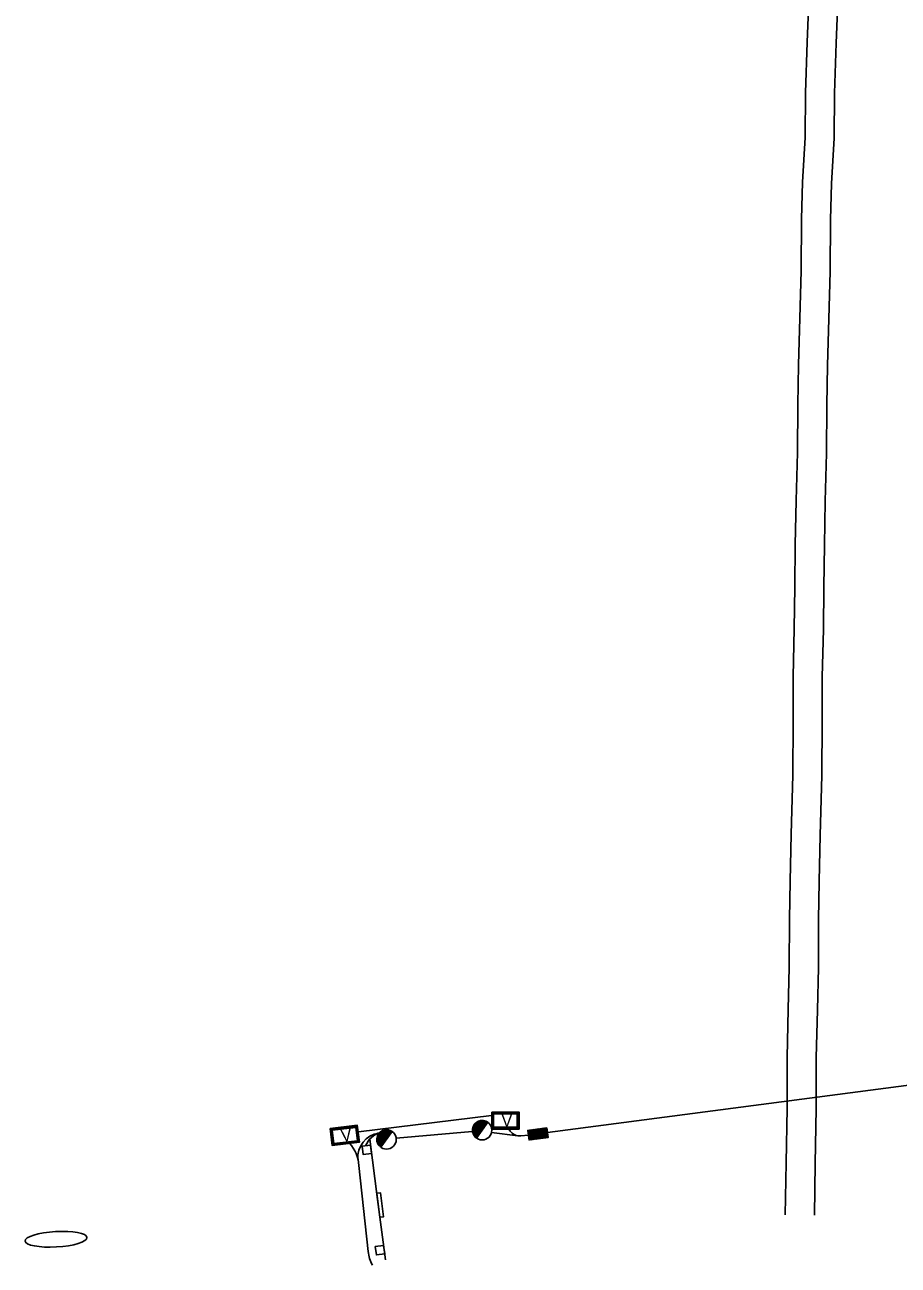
# Model space of a CAD drawing. Extents: x 584850 to 602551, y 145475 to 158627.
# Drawn here: x 585400 to 585761, y 156180 to 156692 of the extents above; entities that cross this region are included whole.
import ezdxf

# ---------------------------------------------------------------- set-up
doc = ezdxf.new("R2010")
doc.units = 0
doc.layers.add('Default', color=7, linetype='Continuous')
doc.layers.add('P_ML_LANE_LINE_50', color=7, linetype='Continuous')

msp = doc.modelspace()

# ---------------------------------------------------------------- linework, layer by layer
at = {"layer": 'Default'}
for p, q in [((585616.41, 156234.38), (585881.92, 156269.31)), ((585538.26, 156234.74), (585593.17, 156241.5)), ((585552.02, 156234.62), (585546.47, 156233.71)), ((585552.11, 156234.88), (585546.65, 156233.98)), ((585551.79, 156235.07), (585546.89, 156234.26)), ((585551.42, 156235.25), (585547.16, 156234.55)), ((585547.38, 156234.72), (585548.26, 156229.38)), ((585547.52, 156228.34), (585552.18, 156234.84)), ((585550.98, 156235.42), (585547.57, 156234.86)), ((585547.6, 156234.89), (585548.46, 156229.66)), ((585547.82, 156235.03), (585548.66, 156229.93)), ((585548.05, 156235.14), (585548.86, 156230.21)), ((585550.32, 156235.56), (585548.16, 156235.2)), ((585548.27, 156235.26), (585549.06, 156230.49)), ((585548.5, 156235.34), (585549.25, 156230.76)), ((585548.73, 156235.42), (585549.45, 156231.04)), ((585548.96, 156235.49), (585549.65, 156231.31)), ((585549.2, 156235.52), (585549.85, 156231.59)), ((585549.44, 156235.56), (585550.04, 156231.86)), ((585549.68, 156235.58), (585550.24, 156232.14)), ((585549.92, 156235.57), (585550.44, 156232.42)), ((585550.16, 156235.57), (585550.64, 156232.69)), ((585550.41, 156235.54), (585550.84, 156232.97)), ((585550.66, 156235.49), (585551.03, 156233.24)), ((585550.92, 156235.44), (585551.23, 156233.52)), ((585551.17, 156235.35), (585551.43, 156233.8)), ((585551.43, 156235.25), (585551.63, 156234.07)), ((585551.7, 156235.13), (585551.82, 156234.35)), ((585551.97, 156234.97), (585552.02, 156234.62)), ((585552.14, 156234.86), (585552.15, 156234.8)), ((585553.87, 156232.08), (585585.25, 156234.85)), ((585589.97, 156236.23), (585585.38, 156235.47)), ((585589.77, 156235.95), (585585.39, 156235.23)), ((585590.16, 156236.5), (585585.4, 156235.72)), ((585585.41, 156235.84), (585585.76, 156233.72)), ((585589.57, 156235.68), (585585.41, 156234.99)), ((585590.36, 156236.78), (585585.42, 156235.96)), ((585589.37, 156235.4), (585585.43, 156234.75)), ((585590.56, 156237.06), (585585.47, 156236.22)), ((585589.18, 156235.12), (585585.48, 156234.52)), ((585590.76, 156237.33), (585585.53, 156236.47)), ((585585.54, 156236.51), (585586.1, 156233.13)), ((585588.98, 156234.85), (585585.55, 156234.28)), ((585590.96, 156237.61), (585585.6, 156236.73)), ((585585.71, 156236.97), (585586.41, 156232.73)), ((585591.15, 156237.88), (585585.72, 156236.99)), ((585591.35, 156238.16), (585585.83, 156237.25)), ((585585.89, 156237.36), (585586.7, 156232.43)), ((585591.55, 156238.43), (585586, 156237.52)), ((585586.08, 156237.65), (585586.98, 156232.2)), ((585591.64, 156238.69), (585586.18, 156237.79)), ((585586.28, 156237.93), (585587.2, 156232.37)), ((585591.32, 156238.88), (585586.42, 156238.08)), ((585586.49, 156238.15), (585587.4, 156232.64)), ((585590.95, 156239.06), (585586.69, 156238.36)), ((585586.7, 156238.37), (585587.59, 156232.92)), ((585586.91, 156238.53), (585587.79, 156233.19)), ((585587.04, 156232.15), (585591.7, 156238.65)), ((585590.51, 156239.24), (585587.09, 156238.67)), ((585587.13, 156238.7), (585587.99, 156233.47)), ((585587.35, 156238.84), (585588.19, 156233.75)), ((585587.57, 156238.96), (585588.38, 156234.02)), ((585589.85, 156239.37), (585587.68, 156239.01)), ((585587.8, 156239.07), (585588.58, 156234.3)), ((585588.03, 156239.15), (585588.78, 156234.57)), ((585588.26, 156239.23), (585588.98, 156234.85)), ((585588.49, 156239.3), (585589.18, 156235.12)), ((585588.73, 156239.33), (585589.37, 156235.4)), ((585588.96, 156239.37), (585589.57, 156235.68)), ((585589.2, 156239.39), (585589.77, 156235.95)), ((585589.45, 156239.39), (585589.97, 156236.23)), ((585589.69, 156239.38), (585590.16, 156236.5)), ((585589.94, 156239.35), (585590.36, 156236.78)), ((585590.19, 156239.3), (585590.56, 156237.06)), ((585590.44, 156239.25), (585590.76, 156237.33)), ((585590.7, 156239.16), (585590.96, 156237.61)), ((585590.96, 156239.06), (585591.15, 156237.88)), ((585591.22, 156238.94), (585591.35, 156238.16)), ((585591.49, 156238.78), (585591.55, 156238.43)), ((585591.67, 156238.68), (585591.68, 156238.61)), ((585600.94, 156235.05), (585600.35, 156235.84)), ((585608.25, 156235.05), (585608.48, 156235.35)), ((585612.44, 156231.84), (585608.25, 156235.05)), ((585612.78, 156231.88), (585608.29, 156235.33)), ((585608.3, 156234.72), (585608.82, 156235.4)), ((585612.1, 156231.79), (585608.3, 156234.72)), ((585608.34, 156234.38), (585609.15, 156235.44)), ((585608.38, 156234.04), (585609.49, 156235.49)), ((585608.43, 156233.71), (585609.83, 156235.53)), ((585608.47, 156233.37), (585610.16, 156235.57)), ((585608.52, 156233.03), (585610.5, 156235.62)), ((585608.56, 156232.7), (585610.84, 156235.66)), ((585608.61, 156232.36), (585611.17, 156235.71)), ((585613.11, 156231.93), (585608.63, 156235.37)), ((585608.65, 156232.02), (585611.51, 156235.75)), ((585608.69, 156231.69), (585611.85, 156235.79)), ((585608.74, 156231.35), (585612.18, 156235.84)), ((585613.45, 156231.97), (585608.96, 156235.42)), ((585609.07, 156231.4), (585612.52, 156235.88)), ((585613.79, 156232.02), (585609.3, 156235.46)), ((585609.41, 156231.44), (585612.86, 156235.93)), ((585614.12, 156232.06), (585609.63, 156235.5)), ((585609.75, 156231.48), (585613.19, 156235.97)), ((585614.46, 156232.1), (585609.97, 156235.55)), ((585610.08, 156231.53), (585613.53, 156236.02)), ((585614.8, 156232.15), (585610.31, 156235.59)), ((585610.42, 156231.57), (585613.86, 156236.06)), ((585615.13, 156232.19), (585610.64, 156235.64)), ((585610.76, 156231.62), (585614.2, 156236.1)), ((585615.47, 156232.24), (585610.98, 156235.68)), ((585611.09, 156231.66), (585614.54, 156236.15)), ((585615.8, 156232.28), (585611.32, 156235.73)), ((585611.43, 156231.71), (585614.87, 156236.19)), ((585616.14, 156232.33), (585611.65, 156235.77)), ((585611.77, 156231.75), (585615.21, 156236.24)), ((585616.48, 156232.37), (585611.99, 156235.81)), ((585612.1, 156231.79), (585615.55, 156236.28)), ((585616.65, 156232.54), (585612.33, 156235.86)), ((585612.44, 156231.84), (585615.88, 156236.33)), ((585616.61, 156232.88), (585612.66, 156235.9)), ((585612.78, 156231.88), (585616.16, 156236.29)), ((585616.56, 156233.21), (585613, 156235.95)), ((585613.11, 156231.93), (585616.2, 156235.95)), ((585616.52, 156233.55), (585613.34, 156235.99)), ((585613.45, 156231.97), (585616.25, 156235.62)), ((585616.47, 156233.89), (585613.67, 156236.04)), ((585613.79, 156232.02), (585616.29, 156235.28)), ((585616.43, 156234.22), (585614.01, 156236.08)), ((585614.12, 156232.06), (585616.33, 156234.94)), ((585616.38, 156234.56), (585614.35, 156236.12)), ((585614.46, 156232.1), (585616.38, 156234.61)), ((585616.34, 156234.9), (585614.68, 156236.17)), ((585616.3, 156235.23), (585615.02, 156236.21)), ((585616.25, 156235.57), (585615.36, 156236.26)), ((585616.21, 156235.9), (585615.69, 156236.3)), ((585616.16, 156236.24), (585616.03, 156236.35)), ((585542.89, 156231.7), (585546.17, 156206.77)), ((585550.44, 156232.42), (585545.86, 156231.66)), ((585550.24, 156232.14), (585545.86, 156231.42)), ((585550.64, 156232.69), (585545.87, 156231.91)), ((585545.88, 156232.03), (585546.23, 156229.91)), ((585550.04, 156231.86), (585545.88, 156231.18)), ((585550.84, 156232.97), (585545.89, 156232.15)), ((585549.85, 156231.59), (585545.91, 156230.94)), ((585551.03, 156233.24), (585545.94, 156232.41)), ((585549.65, 156231.31), (585545.96, 156230.71)), ((585551.23, 156233.52), (585546.01, 156232.66)), ((585546.02, 156232.7), (585546.57, 156229.32)), ((585549.45, 156231.04), (585546.02, 156230.47)), ((585551.43, 156233.8), (585546.08, 156232.91)), ((585549.25, 156230.76), (585546.08, 156230.24)), ((585546.18, 156233.16), (585546.88, 156228.92)), ((585549.06, 156230.49), (585546.18, 156230.01)), ((585551.63, 156234.07), (585546.19, 156233.18)), ((585548.86, 156230.21), (585546.29, 156229.79)), ((585551.82, 156234.35), (585546.3, 156233.44)), ((585546.36, 156233.54), (585547.17, 156228.62)), ((585548.66, 156229.93), (585546.4, 156229.56)), ((585548.46, 156229.66), (585546.55, 156229.34)), ((585546.56, 156233.84), (585547.46, 156228.39)), ((585546.75, 156234.12), (585547.67, 156228.56)), ((585546.96, 156234.34), (585547.87, 156228.83)), ((585547.17, 156234.56), (585548.07, 156229.11)), ((585588.78, 156234.57), (585585.61, 156234.05)), ((585588.58, 156234.3), (585585.71, 156233.82)), ((585588.38, 156234.02), (585585.82, 156233.6)), ((585588.19, 156233.75), (585585.93, 156233.37)), ((585587.99, 156233.47), (585586.08, 156233.16)), ((585587.79, 156233.19), (585586.23, 156232.94)), ((585587.59, 156232.92), (585586.42, 156232.72)), ((585587.4, 156232.64), (585586.62, 156232.51)), ((585587.2, 156232.37), (585586.84, 156232.31)), ((585587.04, 156232.15), (585587.04, 156232.15)), ((585587.04, 156232.15), (585587.04, 156232.15)), ((585593.27, 156234.49), (585604.1, 156233.13)), ((585608.48, 156233.33), (585605.36, 156233.07)), ((585611.77, 156231.75), (585608.34, 156234.38)), ((585611.43, 156231.71), (585608.38, 156234.04)), ((585611.09, 156231.66), (585608.43, 156233.71)), ((585610.76, 156231.62), (585608.47, 156233.37)), ((585610.42, 156231.57), (585608.52, 156233.03)), ((585610.08, 156231.53), (585608.56, 156232.7)), ((585609.75, 156231.48), (585608.61, 156232.36)), ((585609.41, 156231.44), (585608.65, 156232.02)), ((585609.07, 156231.4), (585608.69, 156231.69)), ((585614.8, 156232.15), (585616.42, 156234.27)), ((585615.13, 156232.19), (585616.47, 156233.93)), ((585615.47, 156232.24), (585616.51, 156233.6)), ((585615.8, 156232.28), (585616.56, 156233.26)), ((585616.14, 156232.33), (585616.6, 156232.92)), ((585616.48, 156232.37), (585616.64, 156232.59)), ((585548.26, 156229.38), (585546.71, 156229.13)), ((585548.07, 156229.11), (585546.89, 156228.91)), ((585547.87, 156228.83), (585547.09, 156228.7)), ((585547.67, 156228.56), (585547.31, 156228.5)), ((585547.52, 156228.34), (585547.52, 156228.34)), ((585547.52, 156228.34), (585547.52, 156228.34)), ((585538.45, 156220.79), (585542.26, 156185.28)), ((585546.17, 156206.77), (585549.45, 156181.83))]:
    msp.add_line(p, q, dxfattribs=at)
for points in [[(585593.33, 156242.88), (585604.63, 156242.88), (585604.63, 156235.84), (585593.33, 156235.84)], [(585593.58, 156242.63), (585604.38, 156242.63), (585604.38, 156236.09), (585593.58, 156236.09)], [(585593.83, 156242.38), (585604.13, 156242.38), (585604.13, 156236.34), (585593.83, 156236.34)], [(585594.08, 156242.13), (585603.88, 156242.13), (585603.88, 156236.59), (585594.08, 156236.59)], [(585526.56, 156236.04), (585537.78, 156237.41), (585538.64, 156230.41), (585527.42, 156229.04)], [(585526.84, 156235.82), (585537.57, 156237.13), (585538.36, 156230.63), (585527.63, 156229.32)], [(585527.12, 156235.6), (585537.35, 156236.85), (585538.08, 156230.85), (585527.85, 156229.6)], [(585527.4, 156235.38), (585537.13, 156236.57), (585537.8, 156231.07), (585528.07, 156229.88)], [(585616.15, 156236.36), (585608.22, 156235.32), (585608.74, 156231.35), (585616.67, 156232.4)], [(585543.21, 156229.22), (585543.67, 156225.75), (585540.2, 156225.3), (585539.74, 156228.77)], [(585545.83, 156209.35), (585547.13, 156199.45), (585548.61, 156199.65), (585547.31, 156209.54)], [(585548.66, 156187.78), (585549.12, 156184.31), (585545.65, 156183.85), (585545.19, 156187.32)]]:
    msp.add_lwpolyline(points, close=True, dxfattribs=at)
for centre in [(585549.85, 156231.59), (585589.37, 156235.4)]:
    msp.add_circle(centre, 4, dxfattribs=at)
for centre, radius, start, end in [((585549.85, 156231.59), 4, 54.353, 234.353), ((585589.37, 156235.4), 4, 54.353, 234.353), ((585604.94, 156238.05), 5, 216.9017, 274.8067), ((585524.38, 156220.21), 14.08, 2.3464, 44.0826), ((585548.2, 156224.15), 10.2, 98.7669, 184.7051), ((585549.8, 156225.61), 9.2, 105.5377, 159.0011), ((585557.18, 156186.88), 15, 186.129, 208.8599)]:
    msp.add_arc(centre, radius, start, end, dxfattribs=at)
msp.add_ellipse((585413.28, 156190.35), major_axis=(12.8, 0.72), ratio=0.249166, dxfattribs=at)
at = {"layer": 'P_ML_LANE_LINE_50'}
for points in [[(585714.63, 156200.45), (585714.93, 156221.88), (585715.43, 156244.49), (585715.41, 156265.6), (585715.88, 156285.27), (585716.29, 156302.71), (585716.41, 156322.51), (585716.62, 156338.26), (585717.05, 156357.62), (585717.77, 156382.09), (585717.89, 156404.36), (585717.85, 156422.78), (585718.35, 156442.43), (585718.62, 156459.82), (585718.77, 156477.17), (585719.08, 156495.51), (585719.61, 156515.3), (585719.79, 156535.01), (585720.13, 156551.55), (585720.61, 156570.83), (585721.18, 156590.3), (585721.32, 156611.62), (585721.78, 156626.89), (585722.79, 156645.46), (585722.99, 156663.91), (585723.69, 156684.75), (585724.48, 156705.6)], [(585726.63, 156200.28), (585726.93, 156221.67), (585727.43, 156244.36), (585727.41, 156265.46), (585727.88, 156284.98), (585728.29, 156302.54), (585728.41, 156322.4), (585728.62, 156338.05), (585729.05, 156357.31), (585729.77, 156381.89), (585729.89, 156404.34), (585729.85, 156422.64), (585730.35, 156442.18), (585730.62, 156459.67), (585730.77, 156477.02), (585731.07, 156495.25), (585731.61, 156515.08), (585731.79, 156534.84), (585732.13, 156551.28), (585732.61, 156570.51), (585733.18, 156590.09), (585733.31, 156611.4), (585733.77, 156626.38), (585734.79, 156645.07), (585734.98, 156663.65), (585735.68, 156684.32), (585736.47, 156705.19)]]:
    msp.add_lwpolyline(points, dxfattribs=at)

# ---------------------------------------------------------------- texts
at = {"layer": 'Default'}
for rotation, p in [(360, (585597.36, 156236.88)), (6.9635, (585531.29, 156230.57))]:
    msp.add_text('V', height=4.96, rotation=rotation, dxfattribs=at).set_placement(p)

doc.saveas('drawing.dxf')
